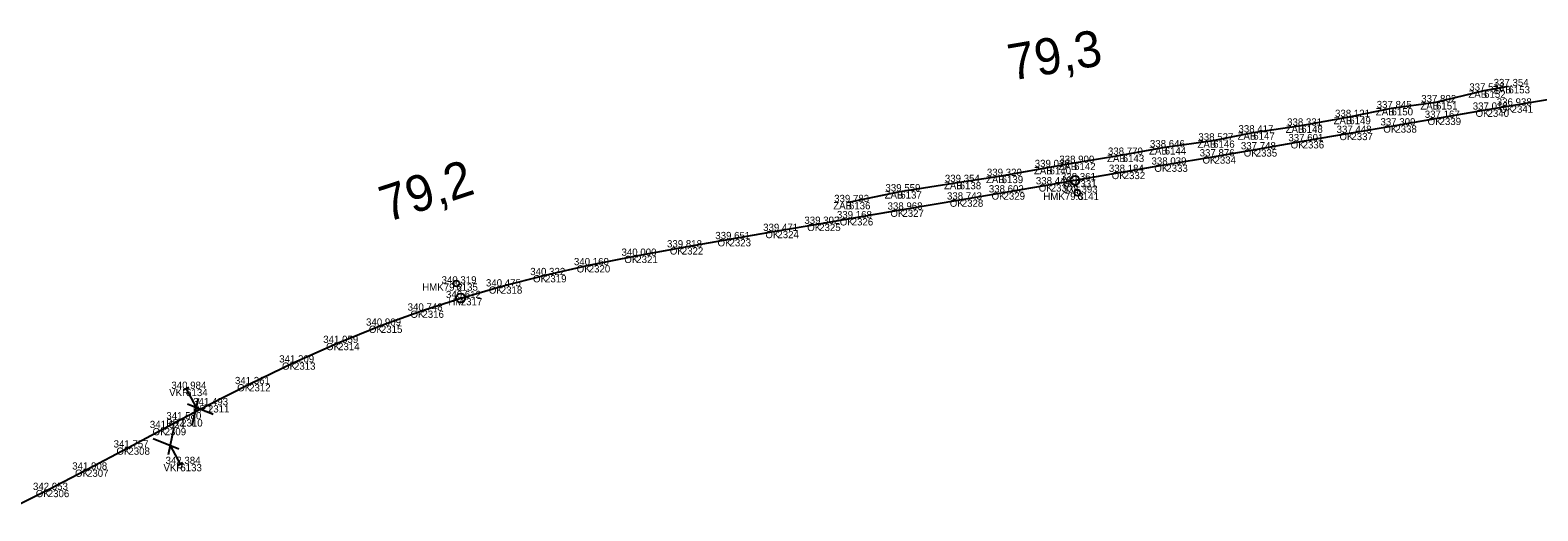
# Model space of a CAD drawing. Extents: x -621782 to -610392, y -1141853 to -1122321.
# Drawn here: x -615196.7 to -614946.5, y -1130038.1 to -1129958.4 of the extents above; entities that cross this region are included whole.
import ezdxf

# ---------------------------------------------------------------- set-up
doc = ezdxf.new("R2010")
doc.units = 0
for name, color, linetype in [('Vrstva 1', 7, 'Continuous'), ('Vrstva 17', 7, 'Continuous'), ('Vrstva 4', 7, 'Continuous'), ('Vrstva 60', 7, 'Continuous'), ('Vrstva 61', 7, 'Continuous'), ('Vrstva 62', 7, 'Continuous'), ('Vrstva 7', 7, 'Continuous')]:
    doc.layers.add(name, color=color, linetype=linetype)

msp = doc.modelspace()

# ---------------------------------------------------------------- linework, layer by layer
at = {"layer": 'Vrstva 1'}
msp.add_lwpolyline([(-615200.71, -1130038.13), (-615193.76, -1130034.67), (-615187.25, -1130031.28), (-615180.38, -1130027.62), (-615174.37, -1130024.39), (-615171.63, -1130022.94), (-615167.19, -1130020.61), (-615160.35, -1130017.1), (-615152.91, -1130013.51), (-615145.59, -1130010.27), (-615138.49, -1130007.4), (-615131.6, -1130004.9), (-615125.24, -1130002.82), (-615118.6, -1130000.89), (-615111.26, -1129999.01), (-615104.01, -1129997.37), (-615096.12, -1129995.8), (-615088.57, -1129994.41), (-615080.65, -1129993.04), (-615072.71, -1129991.68), (-615065.78, -1129990.5), (-615060.38, -1129989.57), (-615051.97, -1129988.14), (-615042.12, -1129986.47), (-615035.19, -1129985.29), (-615027.37, -1129983.95), (-615023.31, -1129983.26), (-615015.26, -1129981.88), (-615008.19, -1129980.67), (-615000.19, -1129979.31), (-614993.36, -1129978.14), (-614985.57, -1129976.79), (-614977.48, -1129975.41), (-614970.19, -1129974.17), (-614962.85, -1129972.91), (-614954.89, -1129971.55), (-614950.9, -1129970.87), (-614943.28, -1129969.58)], dxfattribs=at)
at = {"layer": 'Vrstva 17'}
msp.add_lwpolyline([(-615060.84, -1129986.89), (-615052.32, -1129985.11), (-615042.47, -1129983.56), (-615035.5, -1129982.55), (-615027.55, -1129981.08), (-615023.48, -1129980.38), (-615015.42, -1129979.04), (-615008.45, -1129977.8), (-615000.41, -1129976.67), (-614993.76, -1129975.33), (-614985.79, -1129974.2), (-614977.83, -1129972.77), (-614970.82, -1129971.3), (-614963.44, -1129970.32), (-614955.46, -1129968.39), (-614951.42, -1129967.65)], dxfattribs=at)
at = {"layer": 'Vrstva 4'}
for p, q in [((-615170.36, -1130017.66), (-615171.25, -1130018.13)), ((-615170.8, -1130017.89), (-615169.16, -1130021)), ((-615166.3, -1130022.13), (-615170.59, -1130020.44)), ((-615168.82, -1130019.5), (-615169.83, -1130024)), ((-615171.63, -1130022.94), (-615167.19, -1130020.61)), ((-615173.75, -1130028.76), (-615172.76, -1130024.26)), ((-615176.29, -1130026.15), (-615171.99, -1130027.82)), ((-615171.76, -1130030.36), (-615173.42, -1130027.26)), ((-615172.2, -1130030.6), (-615171.32, -1130030.12))]:
    msp.add_line(p, q, dxfattribs=at)
at = {"layer": 'Vrstva 60'}
for p, q in [((-614951.42, -1129967.65), (-614951.42, -1129967.65)), ((-614963.44, -1129970.32), (-614963.44, -1129970.32)), ((-614955.46, -1129968.39), (-614955.46, -1129968.39)), ((-614977.83, -1129972.77), (-614977.83, -1129972.77)), ((-614970.82, -1129971.3), (-614970.82, -1129971.3)), ((-614962.85, -1129972.91), (-614962.85, -1129972.91)), ((-614954.89, -1129971.55), (-614954.89, -1129971.55)), ((-614950.9, -1129970.87), (-614950.9, -1129970.87)), ((-614993.76, -1129975.33), (-614993.76, -1129975.33)), ((-614985.79, -1129974.2), (-614985.79, -1129974.2)), ((-614977.48, -1129975.41), (-614977.48, -1129975.41)), ((-614970.19, -1129974.17), (-614970.19, -1129974.17)), ((-615008.45, -1129977.8), (-615008.45, -1129977.8)), ((-615000.41, -1129976.67), (-615000.41, -1129976.67)), ((-614985.57, -1129976.79), (-614985.57, -1129976.79)), ((-615023.48, -1129980.38), (-615023.48, -1129980.38)), ((-615015.42, -1129979.04), (-615015.42, -1129979.04)), ((-615000.19, -1129979.31), (-615000.19, -1129979.31)), ((-614993.36, -1129978.14), (-614993.36, -1129978.14)), ((-615035.5, -1129982.55), (-615035.5, -1129982.55)), ((-615027.55, -1129981.08), (-615027.55, -1129981.08)), ((-615015.26, -1129981.88), (-615015.26, -1129981.88)), ((-615008.19, -1129980.67), (-615008.19, -1129980.67)), ((-615052.32, -1129985.11), (-615052.32, -1129985.11)), ((-615042.47, -1129983.56), (-615042.47, -1129983.56)), ((-615035.19, -1129985.29), (-615035.19, -1129985.29)), ((-615027.37, -1129983.95), (-615027.37, -1129983.95)), ((-615023.31, -1129983.26), (-615023.31, -1129983.26)), ((-615022.93, -1129985.34), (-615022.93, -1129985.34)), ((-615060.84, -1129986.89), (-615060.84, -1129986.89)), ((-615042.12, -1129986.47), (-615042.12, -1129986.47)), ((-615065.78, -1129990.5), (-615065.78, -1129990.5)), ((-615060.38, -1129989.57), (-615060.38, -1129989.57)), ((-615051.97, -1129988.14), (-615051.97, -1129988.14)), ((-615072.71, -1129991.68), (-615072.71, -1129991.68)), ((-615088.57, -1129994.41), (-615088.57, -1129994.41)), ((-615080.65, -1129993.04), (-615080.65, -1129993.04)), ((-615104.01, -1129997.37), (-615104.01, -1129997.37)), ((-615096.12, -1129995.8), (-615096.12, -1129995.8)), ((-615125.97, -1130000.4), (-615125.97, -1130000.4)), ((-615111.26, -1129999.01), (-615111.26, -1129999.01)), ((-615125.24, -1130002.82), (-615125.24, -1130002.82)), ((-615118.6, -1130000.89), (-615118.6, -1130000.89)), ((-615131.6, -1130004.9), (-615131.6, -1130004.9)), ((-615138.49, -1130007.4), (-615138.49, -1130007.4)), ((-615145.59, -1130010.27), (-615145.59, -1130010.27)), ((-615152.91, -1130013.51), (-615152.91, -1130013.51)), ((-615170.8, -1130017.89), (-615170.8, -1130017.89)), ((-615160.35, -1130017.1), (-615160.35, -1130017.1)), ((-615171.63, -1130022.94), (-615171.63, -1130022.94)), ((-615167.19, -1130020.61), (-615167.19, -1130020.61)), ((-615174.37, -1130024.39), (-615174.37, -1130024.39)), ((-615180.38, -1130027.62), (-615180.38, -1130027.62)), ((-615171.76, -1130030.36), (-615171.76, -1130030.36)), ((-615187.25, -1130031.28), (-615187.25, -1130031.28)), ((-615193.76, -1130034.67), (-615193.76, -1130034.67))]:
    msp.add_line(p, q, dxfattribs=at)
at = {"layer": 'Vrstva 7'}
for p, q in [((-615022.98, -1129985.35), (-615022.88, -1129985.33)), ((-615126.02, -1130000.41), (-615125.92, -1130000.38))]:
    msp.add_line(p, q, dxfattribs=at)
for centre, radius in [((-615023.31, -1129983.26), 0.75), ((-615022.93, -1129985.34), 0.5), ((-615125.97, -1130000.4), 0.5), ((-615125.24, -1130002.82), 0.75)]:
    msp.add_circle(centre, radius, dxfattribs=at)

# ---------------------------------------------------------------- texts
at = {"layer": 'Vrstva 60'}
for s, p in [('6153', (-614951.42, -1129968.85)), ('6151', (-614963.44, -1129971.53)), ('6152', (-614955.46, -1129969.59)), ('6149', (-614977.83, -1129973.97)), ('6150', (-614970.82, -1129972.5)), ('2339', (-614962.85, -1129974.11)), ('2340', (-614954.89, -1129972.75)), ('2341', (-614950.9, -1129972.07)), ('6147', (-614993.76, -1129976.53)), ('6148', (-614985.79, -1129975.4)), ('2337', (-614977.48, -1129976.61)), ('2338', (-614970.19, -1129975.37)), ('6144', (-615008.45, -1129979)), ('6146', (-615000.41, -1129977.87)), ('2336', (-614985.57, -1129977.99)), ('6142', (-615023.48, -1129981.58)), ('6143', (-615015.42, -1129980.24)), ('2334', (-615000.19, -1129980.51)), ('2335', (-614993.36, -1129979.34)), ('6139', (-615035.5, -1129983.75)), ('6140', (-615027.55, -1129982.28)), ('2332', (-615015.26, -1129983.08)), ('2333', (-615008.19, -1129981.87)), ('6137', (-615052.32, -1129986.31)), ('6138', (-615042.47, -1129984.76)), ('2329', (-615035.19, -1129986.49)), ('2330', (-615027.37, -1129985.15)), ('2331', (-615023.31, -1129984.46)), ('6141', (-615022.93, -1129986.54)), ('6136', (-615060.84, -1129988.09)), ('2328', (-615042.12, -1129987.67)), ('2325', (-615065.78, -1129991.7)), ('2326', (-615060.38, -1129990.77)), ('2327', (-615051.97, -1129989.34)), ('2324', (-615072.71, -1129992.88)), ('2322', (-615088.57, -1129995.6)), ('2323', (-615080.65, -1129994.24)), ('2320', (-615104.01, -1129998.57)), ('2321', (-615096.12, -1129997)), ('6135', (-615125.97, -1130001.6)), ('2319', (-615111.26, -1130000.21)), ('2317', (-615125.24, -1130004.02)), ('2318', (-615118.6, -1130002.09)), ('2316', (-615131.6, -1130006.1)), ('2315', (-615138.49, -1130008.6)), ('2314', (-615145.59, -1130011.47)), ('2313', (-615152.91, -1130014.71)), ('6134', (-615170.8, -1130019.09)), ('2312', (-615160.35, -1130018.3)), ('2310', (-615171.63, -1130024.14)), ('2311', (-615167.19, -1130021.81)), ('2309', (-615174.37, -1130025.59)), ('2308', (-615180.38, -1130028.82)), ('6133', (-615171.76, -1130031.56)), ('2307', (-615187.25, -1130032.48)), ('2306', (-615193.76, -1130035.86))]:
    msp.add_text(s, height=1.2, dxfattribs=at).set_placement(p)
at = {"layer": 'Vrstva 61'}
for s, p in [('337.518', (-614957.92, -1129968.39)), ('337.354', (-614953.87, -1129967.65)), ('337.845', (-614973.28, -1129971.3)), ('337.802', (-614965.89, -1129970.32)), ('337.012', (-614957.34, -1129971.55)), ('336.938', (-614953.36, -1129970.87)), ('338.331', (-614988.14, -1129974.2)), ('338.121', (-614980.19, -1129972.77)), ('337.309', (-614972.65, -1129974.17)), ('337.167', (-614965.3, -1129972.91)), ('338.527', (-615002.86, -1129976.67)), ('338.417', (-614996.21, -1129975.33)), ('337.448', (-614979.93, -1129975.41)), ('338.770', (-615017.87, -1129979.04)), ('338.646', (-615010.9, -1129977.8)), ('337.748', (-614995.81, -1129978.14)), ('337.601', (-614987.93, -1129976.79)), ('339.029', (-615030.01, -1129981.08)), ('338.900', (-615025.93, -1129980.38)), ('338.039', (-615010.64, -1129980.67)), ('337.876', (-615002.65, -1129979.31)), ('339.354', (-615044.92, -1129983.56)), ('339.320', (-615037.95, -1129982.55)), ('338.446', (-615029.82, -1129983.95)), ('338.361', (-615025.66, -1129983.26)), ('338.184', (-615017.71, -1129981.88)), ('339.559', (-615054.78, -1129985.11)), ('338.743', (-615044.57, -1129986.47)), ('338.602', (-615037.63, -1129985.29)), ('338.393', (-615025.38, -1129985.34)), ('339.783', (-615063.29, -1129986.89)), ('338.968', (-615054.43, -1129988.14)), ('339.471', (-615075.07, -1129991.68)), ('339.302', (-615068.23, -1129990.5)), ('339.168', (-615062.83, -1129989.57)), ('339.651', (-615083.01, -1129993.04)), ('340.000', (-615098.57, -1129995.8)), ('339.818', (-615091.02, -1129994.41)), ('340.322', (-615113.71, -1129999.01)), ('340.160', (-615106.46, -1129997.37)), ('340.319', (-615128.42, -1130000.4)), ('340.475', (-615121.06, -1130000.89)), ('340.612', (-615127.69, -1130002.82)), ('340.748', (-615134.05, -1130004.9)), ('340.909', (-615140.95, -1130007.4)), ('341.059', (-615148.05, -1130010.27)), ('341.209', (-615155.36, -1130013.51)), ('340.984', (-615173.25, -1130017.89)), ('341.361', (-615162.7, -1130017.1)), ('341.493', (-615169.64, -1130020.61)), ('341.580', (-615174.08, -1130022.94)), ('341.624', (-615176.82, -1130024.39)), ('341.757', (-615182.83, -1130027.62)), ('341.908', (-615189.7, -1130031.28)), ('342.384', (-615174.21, -1130030.36)), ('342.053', (-615196.21, -1130034.67))]:
    msp.add_text(s, height=1.2, dxfattribs=at).set_placement(p)
at = {"layer": 'Vrstva 62'}
for s, p in [('ZAB', (-614954.02, -1129968.85)), ('ZAB', (-614966.04, -1129971.53)), ('ZAB', (-614958.07, -1129969.59)), ('ZAB', (-614980.44, -1129973.97)), ('ZAB', (-614973.42, -1129972.5)), ('OK', (-614964.83, -1129974.11)), ('OK', (-614956.87, -1129972.75)), ('OK', (-614952.89, -1129972.07)), ('ZAB', (-614996.36, -1129976.53)), ('ZAB', (-614988.39, -1129975.4)), ('OK', (-614979.46, -1129976.61)), ('OK', (-614972.18, -1129975.37)), ('ZAB', (-615011.05, -1129979)), ('ZAB', (-615003.01, -1129977.87)), ('OK', (-614987.55, -1129977.99)), ('ZAB', (-615026.08, -1129981.58)), ('ZAB', (-615018.02, -1129980.24)), ('OK', (-615002.18, -1129980.51)), ('OK', (-614995.34, -1129979.34)), ('ZAB', (-615038.1, -1129983.75)), ('ZAB', (-615030.15, -1129982.28)), ('OK', (-615017.24, -1129983.08)), ('OK', (-615010.17, -1129981.87)), ('ZAB', (-615054.92, -1129986.31)), ('ZAB', (-615045.07, -1129984.76)), ('OK', (-615037.17, -1129986.49)), ('OK', (-615029.35, -1129985.15)), ('HMK79.3', (-615028.59, -1129986.54)), ('HM', (-615025.34, -1129984.46)), ('ZAB', (-615063.44, -1129988.09)), ('OK', (-615044.11, -1129987.67)), ('OK', (-615067.76, -1129991.7)), ('OK', (-615062.36, -1129990.77)), ('OK', (-615053.96, -1129989.34)), ('OK', (-615074.7, -1129992.88)), ('OK', (-615090.55, -1129995.6)), ('OK', (-615082.64, -1129994.24)), ('OK', (-615106, -1129998.57)), ('OK', (-615098.1, -1129997)), ('HMK79.2', (-615131.63, -1130001.6)), ('OK', (-615113.25, -1130000.21)), ('HM', (-615127.28, -1130004.02)), ('OK', (-615120.58, -1130002.09)), ('OK', (-615133.58, -1130006.1)), ('OK', (-615140.48, -1130008.6)), ('OK', (-615147.58, -1130011.47)), ('OK', (-615154.89, -1130014.71)), ('VKR', (-615173.61, -1130019.09)), ('OK', (-615162.33, -1130018.3)), ('PRJ', (-615174.11, -1130024.14)), ('PRJ', (-615169.67, -1130021.81)), ('OK', (-615176.36, -1130025.59)), ('OK', (-615182.36, -1130028.82)), ('VKR', (-615174.56, -1130031.56)), ('OK', (-615189.23, -1130032.48)), ('OK', (-615195.74, -1130035.86))]:
    msp.add_text(s, height=1.2, dxfattribs=at).set_placement(p)
at = {"layer": 'Vrstva 7'}
for s, rotation, p in [('79,3', 9.6818, (-615033.92, -1129966.75)), ('79,2', 18.1232, (-615137.48, -1129990.28))]:
    msp.add_text(s, height=6, rotation=rotation, dxfattribs=at).set_placement(p)

doc.saveas('drawing.dxf')
